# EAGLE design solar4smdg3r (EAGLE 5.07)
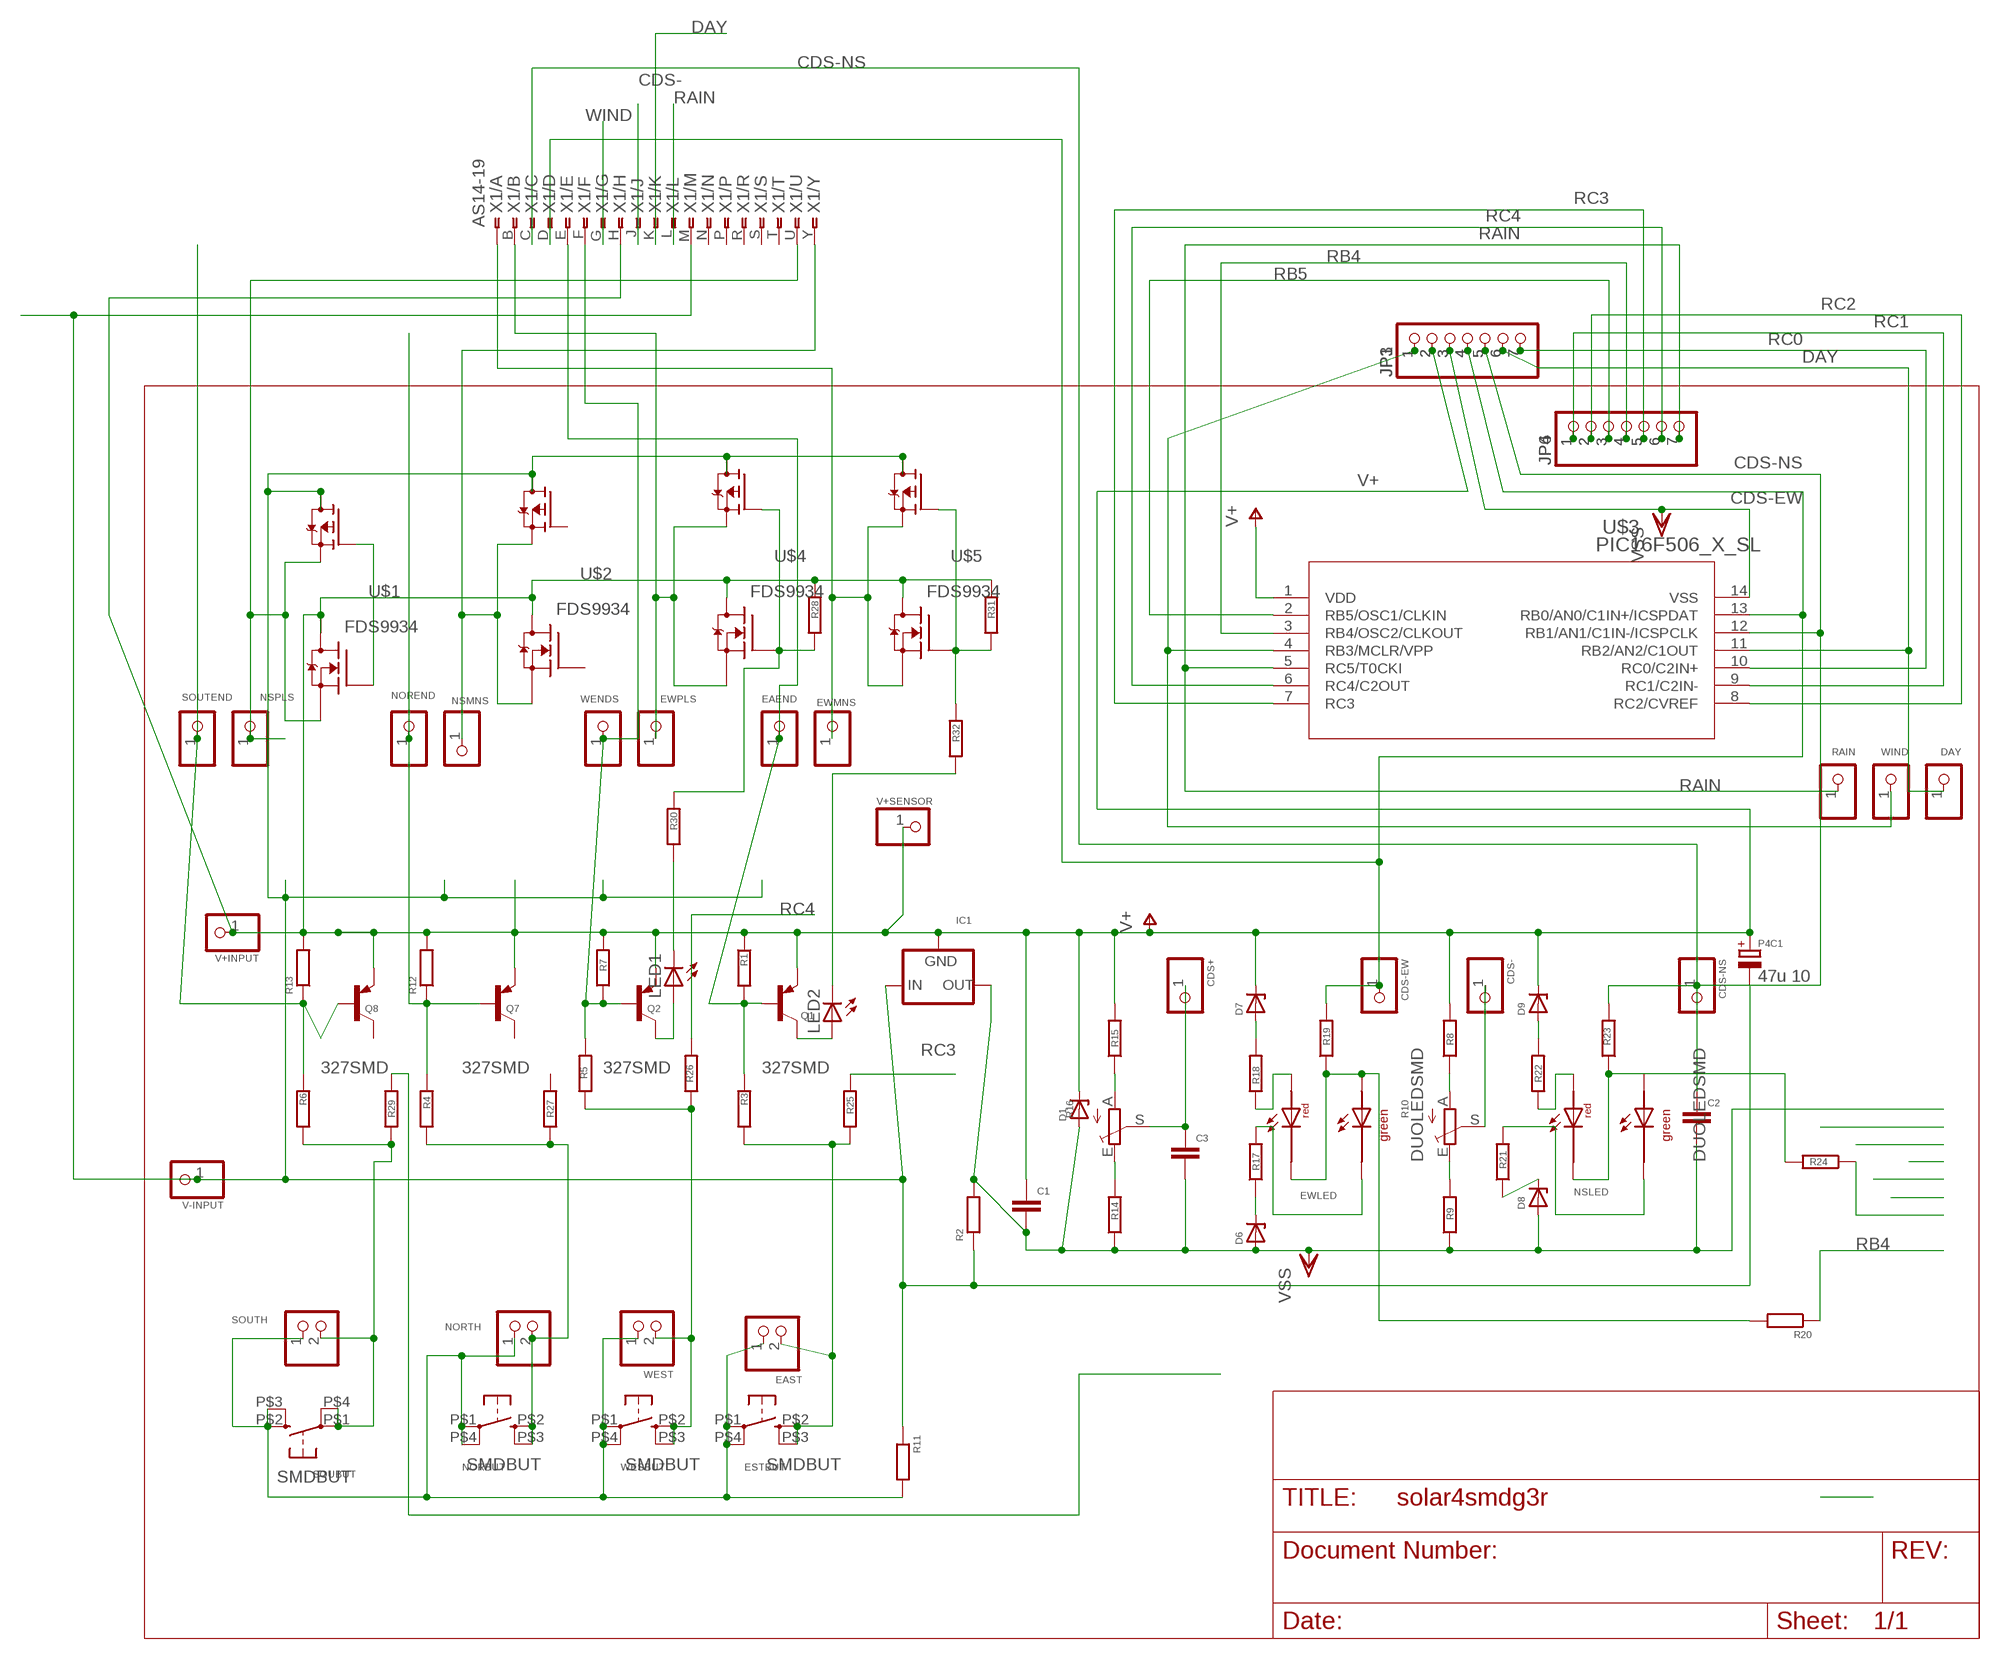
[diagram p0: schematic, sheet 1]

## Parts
C1  C-EUC1206  [C1206]
C2  C-EUC1206  [C1206]
C3  C-EUC1206  [C1206]
CDS+  PINHD-1X1INCH  [1X01]
CDS-  PINHD-1X1INCH  [1X01]
CDS-EW  PINHD-1X1INCH  [1X01]
CDS-NS  PINHD-1X1INCH  [1X01]
D1  ZENER-DIODESOD80C  [SOD80C]
D6  ZENER-DIODESOD80C  [SOD80C]
D7  ZENER-DIODESOD80C  [SOD80C]
D8  ZENER-DIODESOD80C  [SOD80C]
D9  ZENER-DIODESOD80C  [SOD80C]
DAY  PINHD-1X1INCH  [1X01]
EAEND  PINHD-1X1INCH  [1X01]
EAST  PINHD-1X2STR  [1X02]
ESTBUT  SMDBUT  [SMD10/5]
EWLED  DUOLEDSMD  [DUOLEDSMD]
EWMNS  PINHD-1X10MM6  [1X01M]
EWPLS  PINHD-1X10MM6  [1X01M]
IC1  79LXX  [79LXX]
JP1  PINHD-1X7  [1X07]
JP3  PINHD-1X7  [1X07]
JP4  PINHD-1X7  [1X07]
JP6  PINHD-1X7  [1X07]
LED1  LEDCHIPLED_1206  [CHIPLED_1206]
LED2  LEDCHIPLED_1206  [CHIPLED_1206]
NORBUT  SMDBUT  [SMD10/5]
NOREND  PINHD-1X1INCH  [1X01]
NORTH  PINHD-1X2STR  [1X02]
NSLED  DUOLEDSMD  [DUOLEDSMD]
NSMNS  PINHD-1X1INCH  [1X01]
NSPLS  PINHD-1X10MM6  [1X01M]
P4C1  47u 10  CPOL-EUE5-8.5  [E5-8,5]
Q1  327SMD  BC327SMD  [SOT23-BEC]
Q2  327SMD  BC327SMD  [SOT23-BEC]
Q7  327SMD  BC327SMD  [SOT23-BEC]
Q8  327SMD  BC327SMD  [SOT23-BEC]
R1  R-EU_R0805  [R0805]
R2  R-EU_R0805  [R0805]
R3  R-EU_R0805  [R0805]
R4  R-EU_R1206  [R1206]
R5  R-EU_R0805  [R0805]
R6  R-EU_R1206  [R1206]
R7  R-EU_R0805  [R0805]
R8  R-EU_R1206  [R1206]
R9  R-EU_R0805  [R0805]
R10  TRIM_EU-CA6V  [CA6V]
R11  R-EU_R0805  [R0805]
R12  R-EU_R1206  [R1206]
R13  R-EU_R0805  [R0805]
R14  R-EU_R1206  [R1206]
R15  R-EU_R1206  [R1206]
R16  TRIM_EU-CA6V  [CA6V]
R17  R-EU_R1206  [R1206]
R18  R-EU_R1206  [R1206]
R19  R-EU_R0805  [R0805]
R20  R-EU_R0805  [R0805]
R21  R-EU_R1206  [R1206]
R22  R-EU_R1206  [R1206]
R23  R-EU_R0805  [R0805]
R24  R-EU_R0805  [R0805]
R25  R-EU_R0805  [R0805]
R26  R-EU_R0805  [R0805]
R27  R-EU_R0805  [R0805]
R28  R-EU_R0805  [R0805]
R29  R-EU_R0805  [R0805]
R30  R-EU_R0805  [R0805]
R31  R-EU_R0805  [R0805]
R32  R-EU_R0805  [R0805]
RAIN  PINHD-1X1INCH  [1X01]
SOUBUT  SMDBUT  [SMD10/5]
SOUTEND  PINHD-1X1INCH  [1X01]
SOUTH  PINHD-1X2STR  [1X02]
U$1  FDS9934  [SO-8]
U$2  FDS9934  [SO-8]
U$3  PIC16F506_X_SL  [SOIC14_N_MC]
U$4  FDS9934  [SO-8]
U$5  FDS9934  [SO-8]
V+INPUT  PINHD-1X1INCH  [1X01]
V+SENSOR  PINHD-1X10MM6  [1X01M]
V-INPUT  PINHD-1X10MM6  [1X01M]
WENDS  PINHD-1X1INCH  [1X01]
WESBUT  SMDBUT  [SMD10/5]
WEST  PINHD-1X2STR  [1X02]
WIND  PINHD-1X1INCH  [1X01]
X1  AS14-19  AS14-19OLIVE  [Y28M-19TK]

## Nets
CDS-: CDS-.1 R10.S X1.J
CDS-EW: CDS-EW.1 JP1.4 JP3.4 R19.2 U$3.13(RB0/AN0/C1IN+/ICSPDAT) X1.D
CDS-NS: C2.1 CDS-NS.1 JP1.5 JP3.5 R23.2 U$3.12(RB1/AN1/C1IN-/ICSPCLK) X1.C
DAY: DAY.1 JP1.6 JP3.6 U$3.11(RB2/AN2/C1OUT) X1.K
MOTO1: EWPLS.1 U$4.1(Q1S) U$4.3(Q2S) X1.B
MOTOR1: NSPLS.1 U$1.1(Q1S) U$1.3(Q2S) X1.U
MOTOR2: NSMNS.1 U$2.1(Q1S) U$2.3(Q2S) X1.Y
MOTOR3: EWMNS.1 U$5.1(Q1S) U$5.3(Q2S) X1.A
N$1: R9.2 R10.E
N$6: EWLED.AGRN EWLED.CRED R19.1 R20.2
N$9: R6.1 R29.1 SOUBUT.P$1(P) SOUBUT.P$4(P1) SOUTH.2
N$10: LED1.A Q2.C
N$11: EAST.2 ESTBUT.P$2(S) ESTBUT.P$3(S1) R3.1 R25.1
N$13: R24.1
N$14: D7.A R18.2
N$17: NORBUT.P$2(S) NORBUT.P$3(S1) NORTH.2 R4.1 R27.1
N$18: R8.1 R10.A
N$19: Q8.B R6.2 R13.1 SOUTEND.1
N$20: NOREND.1 Q7.B R4.2 R12.1
N$21: R14.2 R16.E
N$22: R15.1 R16.A
N$23: C3.1 CDS+.1 R16.S
N$25: EWLED.ARED R18.1
N$27: D6.C R17.1
N$28: EWLED.CGRN R17.2
N$29: EAST.1 ESTBUT.P$1(P) ESTBUT.P$4(P1) NORBUT.P$1(P) NORBUT.P$4(P1) NORTH.1 R11.2 SOUBUT.P$2(S) SOUBUT.P$3(S1) SOUTH.1 WESBUT.P$1(P) WESBUT.P$4(P1) WEST.1
N$30: NSLED.AGRN NSLED.CRED R23.1 R24.2
N$32: Q2.B R5.2 R7.1 WENDS.1 X1.F
N$33: EAEND.1 Q1.B R1.2 R3.2 X1.E
N$35: R29.2
N$37: LED2.A Q1.C
N$39: R5.1 R26.1 WESBUT.P$2(S) WESBUT.P$3(S1) WEST.2
N$41: D9.A R22.2
N$42: NSLED.ARED R22.1
N$43: D8.C R21.1
N$44: NSLED.CGRN R21.2
N$50: U$1.2(Q1G) U$1.4(Q2G)
N$51: LED1.C R30.1
N$54: R28.1 R30.2 U$4.2(Q1G) U$4.4(Q2G)
N$55: R31.1 R32.2 U$5.2(Q1G) U$5.4(Q2G)
N$56: LED2.C R32.1
RAIN: JP4.7 JP6.7 RAIN.1 U$3.5(RC5/T0CKI) X1.L
RB4: JP4.4 JP6.4 R20.1 U$3.3(RB4/OSC2/CLKOUT)
RB5: JP4.3 JP6.3 U$3.2(RB5/OSC1/CLKIN)
RC0: JP1.7 JP3.7 U$3.10(RC0/C2IN+)
RC1: JP4.1 JP6.1 U$3.9(RC1/C2IN-)
RC2: JP4.2 JP6.2 U$3.8(RC2/CVREF)
RC3: JP4.5 JP6.5 R25.2 U$3.7(RC3)
RC4: JP4.6 JP6.6 R26.2 U$3.6(RC4/C2OUT)
V+: C1.1 D1.C D7.C D9.C IC1.GND JP1.2 JP3.2 P4C1.+ Q1.E Q2.E Q7.E Q8.E R1.1 R7.2 R8.2 R12.2 R13.2 R15.2 R28.2 R31.2 U$1.7(Q1D2) U$1.8(Q1D1) U$2.7(Q1D2) U$2.8(Q1D1) U$3.1(VDD) U$4.7(Q1D2) U$4.8(Q1D1) U$5.7(Q1D2) U$5.8(Q1D1) V+INPUT.1 V+SENSOR.1 X1.H
V-: IC1.IN P4C1.- R2.1 R11.1 U$1.5(Q2D2) U$1.6(Q2D) U$2.5(Q2D2) U$2.6(Q2D) U$4.5(Q2D2) U$4.6(Q2D) U$5.5(Q2D2) U$5.6(Q2D) V-INPUT.1 X1.M
VSS: C1.2 C2.2 C3.2 D1.A D6.A D8.A IC1.OUT JP1.3 JP3.3 R2.2 R9.1 R14.1 U$3.14(VSS)
WIND: JP1.1 JP3.1 U$3.4(RB3/MCLR/VPP) WIND.1 X1.G
Unconnected: Q7.C Q8.C R27.2 U$2.2(Q1G) U$2.4(Q2G) X1.N X1.P X1.R X1.S X1.T

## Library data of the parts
C1-C3 = rcl-2:C-EU: CAPACITOR, European symbol
CDS+ CDS- CDS-EW CDS-NS DAY EAEND EWMNS EWPLS NOREND NSMNS NSPLS RAIN SOUTEND V+INPUT V+SENSOR V-INPUT WENDS WIND = pinhead(2):PINHD-1X1: PIN HEADER
D1 D6-D9 = diode-1:ZENER-DIODE: Z-Diode
EAST NORTH SOUTH WEST = pinhead:PINHD-1X2: PIN HEADER
ESTBUT NORBUT SOUBUT WESBUT = switch-omron:SMDBUT
EWLED NSLED = led:DUOLEDSMD
IC1 = v-reg:79LXX: VOLTAGE REGULATOR
JP1 JP3 JP4 JP6 = pinhead:PINHD-1X7: PIN HEADER
LED1 LED2 = led:LED: LED
P4C1 = rcl:CPOL-EU: POLARIZED CAPACITOR, European symbol
Q1 Q2 Q7 Q8 = transistor-pnp:BC327*: PNP Transistror
R1-R9 R11-R15 R17-R32 = rcl-2:R-EU_: RESISTOR, European symbol
R10 R16 = pot:TRIM_EU-: POTENTIOMETER
U$1 U$2 U$4 U$5 = transistor-fet:FDS9934
U$3 = pic16f506mc:PIC16F506_X_SL
X1 = con-deutsch:AS14-19: DEUTSCH Connector

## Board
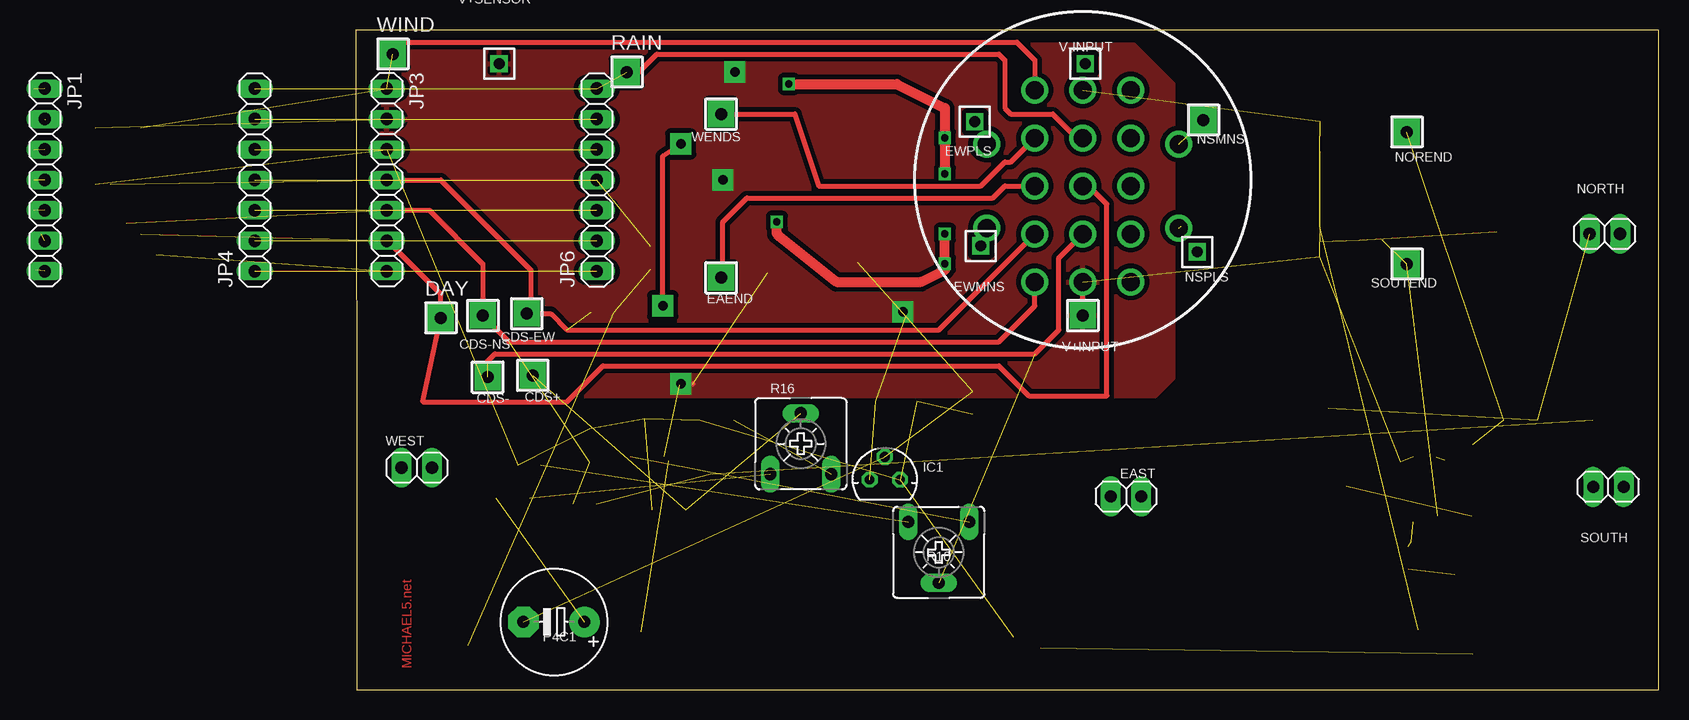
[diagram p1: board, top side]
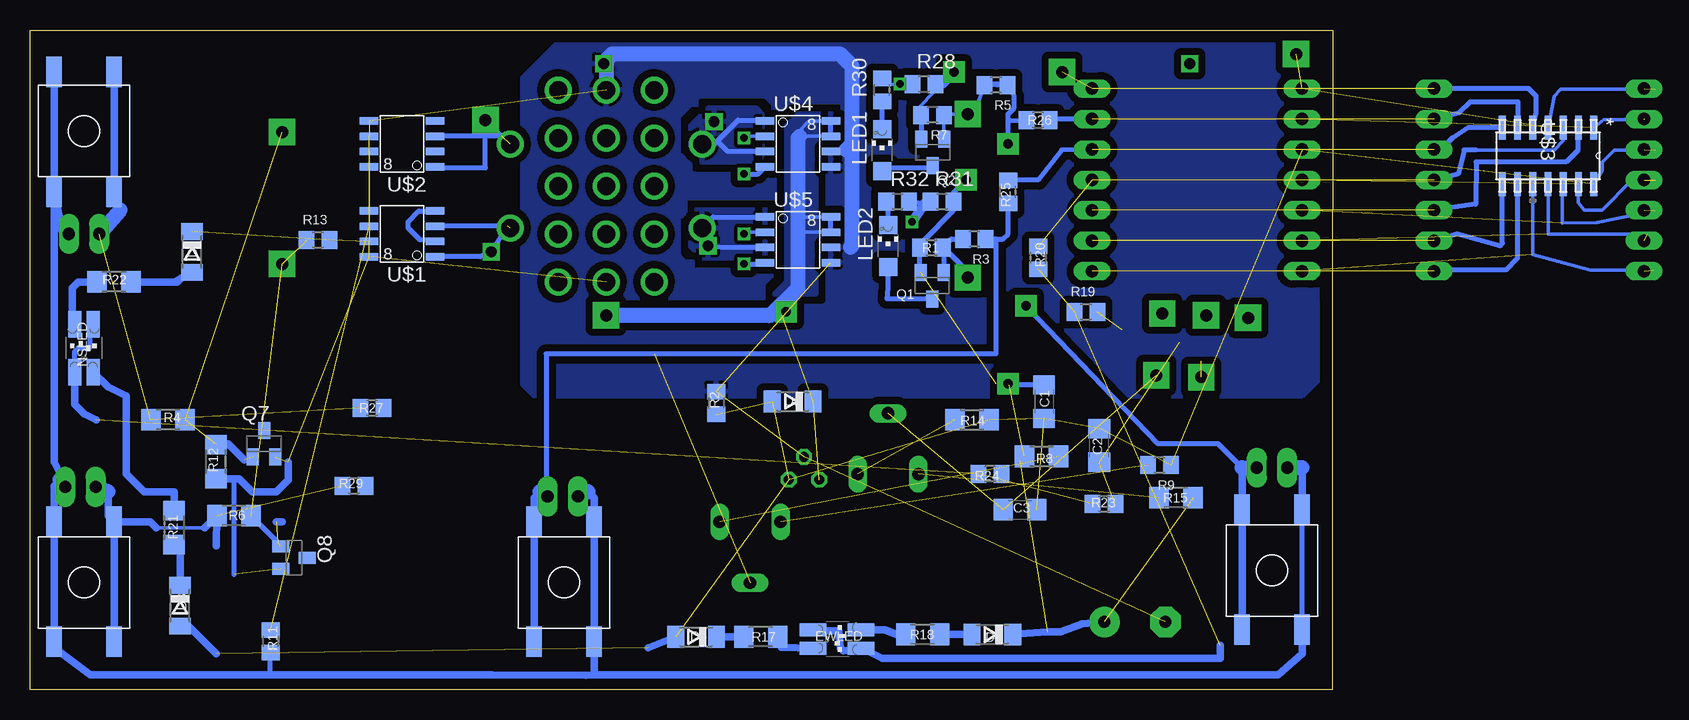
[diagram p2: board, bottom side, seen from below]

Size 108.57 x 55 mm. Coordinates in mm from the lower left corner, seen from the top.
Outline: 0.07,0 108.57,0 108.57,55 0,55 0.07,25 0.07,0
Copper layers (1*16): Top 0.035mm / dielectric 1.5mm / Bottom 0.035mm
Design rules "default *": minimum track width 40mil, minimum drill 30mil, track to track 8mil, track to pad 8mil, pad to pad 8mil, via to via 8mil, smd to smd 8mil, copper to edge 40mil, drill to drill 8mil, minimum pad ring 10mil, minimum via ring 8mil, stop-mask expansion 4mil, vias tented up to drill 0mil, thermal gap 10mil

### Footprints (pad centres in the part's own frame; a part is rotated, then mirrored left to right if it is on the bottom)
C1206 = smd 1.6 x 1.8: 1 -1.4,0; 2 1.4,0
1X01 = drill 1 pad 2.184 square: 1 0,0
SOD80C = smd 1.4 x 1.8: A 1.7,0; C -1.7,0
1X02 = drill 1.016 pad 1.676 long: 1 -1.27,0; 2 1.27,0
SMD10/5 = smd 1.27 x 2.54: P$1 -2.5,0; P$2 2.5,0; P$3 2.5,10; P$4 -2.5,10
DUOLEDSMD = smd 1.067 x 2.184: AGRN 0.77,1.95; ARED -0.77,1.95; CGRN 0.77,-2.05; CRED -0.77,-2.05
1X01M = drill 0.914 square: 1 0,0
79LXX = drill 0.813 octagon: GND -1.27,0; IN 0,1.905; OUT 1.27,0
1X07 = drill 1.016 long: 1 -7.62,0; 2 -5.08,0; 3 -2.54,0; 4 0,0; 5 2.54,0; 6 5.08,0; 7 7.62,0
CHIPLED_1206 = smd 1.5 x 1.5: A 0,-1.75; C 0,1.75
E5-8,5 = drill 1 pad 2.54 round: + -2.54,0 | drill 1 pad 2.54 octagon: - 2.54,0
SOT23-BEC = smd 1 x 1.4: B -0.95,-1.1; C 0,1.1; E 0.95,-1.1
R0805 = smd 1.3 x 1.5: 1 -0.95,0; 2 0.95,0
R1206 = smd 1.6 x 1.803: 1 -1.422,0; 2 1.422,0
CA6V = drill 1.016 long: A -2.54,-2.54; E 2.54,-2.54; S 0,2.54
SO-8 = smd 1.524 x 0.61: 1 -2.743,1.905; 2 -2.743,0.635; 3 -2.743,-0.635; 4 -2.743,-1.905; 5 2.743,-1.905; 6 2.743,-0.635; 7 2.743,0.635; 8 2.743,1.905
SOIC14_N_MC = smd 1.981 x 0.559: 1 -2.362,3.81; 2 -2.362,2.54; 3 -2.362,1.27; 4 -2.362,0; 5 -2.362,-1.27; 6 -2.362,-2.54; 7 -2.362,-3.81; 8 2.362,-3.81; 9 2.362,-2.54; 10 2.362,-1.27; 11 2.362,0; 12 2.362,1.27; 13 2.362,2.54; 14 2.362,3.81
Y28M-19TK = drill 1.5 pad 2.184 round: A -8,-3.5; B -8,3.5; C -4,-8; D -4,-4; E -4,0; F -4,4; G -4,8; H 0,-8; J 0,-4; K 0,0; L 0,4; M 0,8; N 4,-8; P 4,-4; R 4,0; S 4,4; T 4,8; U 8,-3.5; Y 8,3.5

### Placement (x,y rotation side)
C1  24.07,24 270 bottom
C2  19.46,20.35 90 bottom
C3  26.07,15 0 bottom
CDS+  14.72,26.2 0 top
CDS-  10.97,26.05 90 top
CDS-EW  14.22,31.35 0 top
CDS-NS  10.57,31.2 90 top
D1  45.02,24.02 180 bottom
D6  53.07,4.4 180 bottom
D7  28.37,4.6 180 bottom
D8  96.07,7 270 bottom
D9  95.07,36.5 270 bottom
DAY  7.07,31 0 top
EAEND  30.42,34.35 90 top
EAST  64.17,16.1 0 top
ESTBUT  64.07,14 180 bottom
EWLED  41.27,4.2 270 bottom
EWMNS  52.07,37 90 top
EWPLS  51.57,47.35 90 top
IC1  44.07,17.5 0 top
JP1  not placed on the board
JP3  2.57,42.5 270 top
JP4  -8.43,42.5 90 top  (outside the outline)
JP6  20.07,42.5 90 top
LED1  37.57,45 0 bottom
LED2  37.07,37 0 bottom
NORBUT  104.07,41.5 0 bottom
NOREND  87.57,46.5 0 top
NORTH  104.07,38 180 top
NSLED  104.07,28.5 0 bottom
NSMNS  70.62,47.5 0 top
NSPLS  70.12,36.5 0 top
P4C1  16.49,5.64 180 top
Q1  33.38,33.67 180 bottom
Q2  33.34,44.79 180 bottom
Q7  89.07,20.5 0 bottom
Q8  86.57,11 270 bottom
R1  33.46,36.85 0 bottom
R2  51.39,23.89 270 bottom
R3  29.88,37.56 180 bottom
R4  97.07,22.5 0 bottom
R5  28.07,50.4 180 bottom
R6  91.57,14.5 0 bottom
R7  33.36,47.91 180 bottom
R8  24.28,19.44 180 bottom
R9  14.44,18.71 180 bottom
R10  48.56,11.44 180 top
R11  88.52,4.02 270 bottom
R12  93.07,19 270 bottom
R13  84.57,37.5 0 bottom
R14  30.07,22.5 180 bottom
R15  13.07,16 0 bottom
R16  37.07,20.5 0 top
R17  47.67,4.4 0 bottom
R18  34.17,4.6 0 bottom
R19  20.57,31.5 0 bottom
R20  24.57,36 270 bottom
R21  96.57,13.5 90 bottom
R22  101.57,34 0 bottom
R23  19.07,15.5 0 bottom
R24  28.57,18 180 bottom
R25  27.07,41.5 90 bottom
R26  24.57,47.5 0 bottom
R27  80.07,23.5 0 bottom
R28  34.07,50.5 0 bottom
R29  81.57,17 0 bottom
R30  37.57,50 90 bottom
R31  32.57,40.7 0 bottom
R32  36.27,40.7 0 bottom
RAIN  22.57,51.5 0 top
SOUBUT  104.07,14 180 bottom
SOUTEND  87.57,35.5 0 top
SOUTH  104.37,16.9 180 top
U$1  77.57,38 180 bottom
U$2  77.57,45.5 180 bottom
U$3  -17.93,44.5 270 bottom  (outside the outline)
U$4  44.57,45.5 0 bottom
U$5  44.57,37.5 0 bottom
V+INPUT  60.57,31.2 90 top
V+SENSOR  11.92,52.2 90 top
V-INPUT  60.77,52.2 90 top
WENDS  30.42,48 90 top
WESBUT  5.07,15 180 bottom
WEST  5.07,18.5 0 top
WIND  3.07,53 0 top
X1  60.57,42 0 top

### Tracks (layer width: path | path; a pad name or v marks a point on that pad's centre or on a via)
CDS-  (2 unrouted)
  Top 0.406: X1.J 58.57,36 58.57,30 56.57,28 11.57,28 10.97,27.4
CDS-EW  (3 unrouted)
  Top 0.406: JP3.4 7.07,42.5 14.57,35 14.57,31.7 CDS-EW.1 16.22,31.35 17.57,30 48.57,30 X1.D
  Bottom 0.305: U$3.13 -20.43,40.6 -20.93,40 -22.43,40 -24.89,42.46 -26.86,42.46
CDS-NS  (4 unrouted)
  Top 0.406: X1.C 56.57,32 53.57,29 12.77,29 CDS-NS.1 10.57,35.5 6.11,39.96 JP3.5
  Bottom 0.305: U$3.12 -19.13,41.31 -19.13,38.9 -22.01,38.92 -26.86,39.92
DAY  (2 unrouted)
  Top 0.406: JP3.6 2.99,37 3.07,37 7.07,33 DAY.1 5.57,24 17.57,24 20.57,27 53.57,27 56.07,24.5 62.57,24.5 62.57,40.5 61.07,42 X1.K
  Bottom 0.305: U$3.11 -17.93,38 -26.24,38
MOTO1
  Bottom 0.406: X1.B 51.57,45.5 51.32,45.75 | 51.32,45.75 49.57,47.5 47.41,47.5 U$4.1 | U$4.3 50.44,44.87 51.32,45.75
  pour Bottom (isolate 0.305): 47.57,47.5 47.57,48 48.07,48.5 52.07,48.5 53.57,47 53.57,45 52.57,44 48.07,44 47.57,44.5
MOTOR1  (1 unrouted)
  Bottom 0.406: U$1.3 68.75,38.63 NSPLS.1 71.02,36.09 U$1.1
MOTOR2  (1 unrouted)
  Bottom 0.406: U$2.1 74.97,43.59 75.07,43.5 70.62,43.5 NSMNS.1 69.25,46.13 U$2.3
MOTOR3
  Bottom 0.406: U$5.3 50.94,36.87 EWMNS.1 51.66,39.41 U$5.1
  pour Bottom (isolate 0.305): 47.07,40 53.07,40 53.57,39.5 53.57,37 52.57,36 47.57,36 47.07,36.5
N$1  (1 unrouted)
N$6  (2 unrouted)
  Bottom 0.61: EWLED.CRED 42.95,4.9 41.17,4.9 41.07,3.5 40.8,3.23 EWLED.AGRN 38.8,3.23 37.57,2.6 9.37,2.6 9.37,3.7
N$9  (1 unrouted)
  Bottom 0.305: 98.07,13.5 93.99,13.5
  Bottom 0.61: SOUBUT.P$1 98.57,14 98.07,13.5 | 93.99,13.5 R6.1 93.07,12 | SOUBUT.P$4 SOUBUT.P$1 | SOUBUT.P$1 102.07,14.5 102.07,16.5
  Bottom 1.27: 102.07,16.5 SOUTH.2
N$10
  Bottom 0.406: Q2.C 33.54,43.5 37.07,43.5 LED1.A
N$11
  Bottom 0.406: R25.1 27.07,38 27.51,37.56 28.07,37.56 | 28.07,37.56 R3.1 | EAST.2 65.57,16.23 65.57,28 28.07,28 28.07,37.56
  Bottom 0.61: ESTBUT.P$3 ESTBUT.P$2 66.57,16 66.07,16.5
  Bottom 1.27: EAST.2 66.07,16.5
N$14
  Bottom 0.61: D7.A R18.2
N$17  (2 unrouted)
  Bottom 0.61: NORBUT.P$2 NORBUT.P$3 | NORBUT.P$2 101.57,41 | 101.07,40 NORBUT.P$2
  Bottom 1.27: NORTH.2 101.07,40
N$18  (1 unrouted)
N$19  (4 unrouted)
  Bottom 0.406: 87.92,12.27 R6.2
  Bottom 0.61: 87.57,14 88.07,14
N$20  (3 unrouted)
  Bottom 0.61: 90.72,19.15 92.07,20.5 92.99,20.5 R12.1
N$21  (1 unrouted)
N$22  (1 unrouted)
N$23  (2 unrouted)
N$25
  Bottom 0.61: R18.1 35.49,4.42 36.07,4.5 37.35,5 EWLED.ARED
N$27
  Bottom 0.61: R17.1 D6.C
N$28
  Bottom 0.61: EWLED.CGRN 45.98,3.53 R17.2
N$29
  Bottom 0.406: WESBUT.P$4 WESBUT.P$1 | R11.2 88.57,2.6 88.57,1.25
  Bottom 0.61: WESBUT.P$1 2.57,18.5 | 61.57,1.25 ESTBUT.P$4 ESTBUT.P$1 61.57,16 62.07,16.5 | 61.57,1.25 4.57,1.25 2.57,3 WESBUT.P$4 | 61.57,1.25 62.27,1.2 70.07,1.23 73.57,1.25 88.57,1.25 103.57,1.25 106.57,3.5 SOUBUT.P$3 SOUBUT.P$2 106.57,17 106.07,17.5 | SOUTH.1 106.07,18 106.57,19 NORBUT.P$1 | NORBUT.P$1 106.07,39 | NORBUT.P$1 NORBUT.P$4
  Bottom 1.27: 2.57,18.5 WEST.1 | 62.07,16.5 EAST.1 | 106.07,17.5 SOUTH.1 | 106.07,39 NORTH.1
N$30  (2 unrouted)
  Bottom 0.406: NSLED.CRED 104.84,28.23 104.57,28.5 103.57,28.5 103.57,30.18 NSLED.AGRN
  Bottom 0.61: NSLED.CRED 104.84,23.77 104.07,23 103.07,22.5
N$32
  Top 0.406: X1.F 54.57,44 54.07,44 52.07,42 38.57,42 36.57,48 WENDS.1
  Bottom 0.305: Q2.B 32.41,45.91 R7.1 32.33,48 WENDS.1 30.42,48.35 29.57,49 29.07,50.35 R5.2
N$33
  Top 0.406: X1.E 54.07,42 53.07,41 32.57,41 30.57,39 30.57,34.5 EAEND.1
  Bottom 0.406: 32.43,36.86 Q1.B | 32.43,36.86 32.43,37.27 R1.2 31.8,37.56 R3.2 | 32.43,36.86 30.57,35 30.57,34.5 EAEND.1
N$37
  Bottom 0.406: Q1.C 37.14,32.57 37.07,33.5 LED2.A
N$39  (via drill 0.8 pad 1.78)
  Top 0.406: v27.07,45.5 25.57,44.5 v25.57,32
  Bottom 0.406: R5.1 29.02,50.5 27.07,50.5 26.57,49.5 26.57,48.5 27.07,48 27.07,47.45 | 27.07,47.45 R26.1 | v27.07,45.5 27.07,47.45 | v25.57,32 14.57,20.5 9.57,20.5 7.57,18.5
  Bottom 0.61: WESBUT.P$3 WESBUT.P$2 7.57,18.5
  Bottom 1.27: 7.57,18.5 WEST.2
N$41
  Bottom 0.61: D9.A 95.97,34.32 | 95.97,34.32 96.57,34 | R22.2 96.29,34 95.97,34.32
N$42
  Bottom 0.61: R22.1 104.57,34 105.07,33.5 105.07,30.68 NSLED.ARED
N$43
  Bottom 0.61: D8.C 96.07,11.58 R21.1
N$44
  Bottom 0.61: R21.2 96.57,16.5 99.07,16.5 100.57,18 100.57,24.5 102.07,25.22 NSLED.CGRN
N$50
  Bottom 0.406: U$1.4 76.16,39.91 77.07,39 77.07,38.5 76.07,37.5 74.96,37.5 U$1.2
N$51
  Bottom 0.406: LED1.C R30.1
N$54  (via drill 0.6)
  Top 0.813: v36.07,50.5 45.07,50.5 49.07,48.5 v49.07,46 v49.07,43
  Bottom 0.305: U$4.2 48.94,46.13 v49.07,46 | R30.2 37.12,50.5 v36.07,50.5 R28.1
  Bottom 0.406: U$4.4 47.91,43 v49.07,43
N$55  (via drill 0.6)
  Top 0.406: 49.07,35 v49.07,35.5
  Top 0.813: 49.07,35 47.07,34 40.07,34 35.07,38 v35.07,39 | v49.07,35.5 v49.07,38
  Bottom 0.305: U$5.2 48.94,38.13 v49.07,38
  Bottom 0.406: R32.2 34.07,40.5 R31.1 | U$5.4 47.41,35.5 v49.07,35.5
  Bottom 0.813: v35.07,39 34.07,40.5
N$56
  Bottom 0.406: LED2.C 37.07,40 R32.1
RAIN  (2 unrouted)
  Top 0.406: RAIN.1 23.57,51.5 25.07,53 53.57,53 54.07,52.5 54.07,48.5 54.57,48 58.07,48 60.07,46 X1.L
  Bottom 0.406: JP4.7 -16.31,50.12 -16.93,49.5 -16.93,48.09 U$3.5
RB4  (2 unrouted)
  Bottom 0.305: U$3.3 -19.2,45.77 -18.43,45 -11.93,45
  Bottom 0.406: -11.93,45 -10.93,45 -10.43,43 JP4.4
RB5  (1 unrouted)
  Bottom 0.406: JP4.3 -11.89,40.46 -11.93,44 -19.43,44 -20.43,45 -20.43,46.82 U$3.2
RC0  (2 unrouted)
  Bottom 0.305: U$3.10 -16.66,36.27 -21.43,35 -26.7,35
RC1  (1 unrouted)
  Bottom 0.406: U$3.9 -15.39,35.96 -14.43,35 -8.55,35 JP4.1 | JP6.1 20.9,34.88
RC2  (1 unrouted)
  Bottom 0.406: U$3.8 -14.12,37.19 -13.93,37 -10.35,38 JP4.2
RC3  (1 unrouted)
  Bottom 0.406: U$3.7 -11.29,46.86 -9.93,46 -9.47,45.5 JP4.5 | JP6.5 22.61,45 24.57,42.5 27.07,42.5 R25.2
RC4  (1 unrouted)
  Bottom 0.406: JP4.6 -10.51,48.08 -11.43,49 -15.43,49 -15.43,46.9 U$3.6 | R26.2 23.54,47.58 JP6.6
V+  (via drill 0.8 pad 1.78)  (17 unrouted)
  Top 0.406: V+INPUT.1 X1.H | v27.07,25.5 28.07,25.5
  Bottom 0.305: 44.44,46.13 U$4.7 | U$4.8 43.66,47.41 44.57,46.5 44.57,46 | U$5.8 44.48,39.41 44.57,39.5 | U$5.7 44.44,38.13 44.57,38 | R28.2 33.12,49.95 34.57,48.5 34.57,48.17 R7.2 | U$3.1 -22.56,47.54 -25.89,47.54 -26.43,47 -26.46,47
  Bottom 0.406: R8.2 26.07,19.07 | 91.57,9.6 91.57,17.58 | Q2.E 34.31,46.41 R7.2 | U$5.7 U$5.8 | U$4.7 U$4.8 | v45.57,31.5 45.87,31.2 47.07,31.2 | v30.57,42.5 31.62,41.45 R31.2 31.62,39.95 34.07,37.5 34.07,37.19 R1.1 34.41,34.85 Q1.E | C1.1 26.97,25.4 v27.07,25.5
  Bottom 0.61: D7.C 23.77,4.8 22.67,4.8 20.89,5.5 P4C1.+ | R12.2 91.57,17.58 91.15,17.58 90.07,16.5 88.07,16.5 87.07,17.5 87.07,19
  Bottom 0.813: R28.2 32.57,50.5 v31.57,51.5
  Bottom 1.27: V+INPUT.1 47.07,31.2 46.87,31.2 44.57,33.5 44.57,38 44.57,39.5 44.57,46 44.44,46.13
  pour Bottom (isolate 0.61): 41.57,48 44.57,48 45.57,47 45.57,34 46.57,33 43.07,33 43.07,46 41.57,47.5
  pour Top (isolate 0.406): 2.57,54 64.57,54 68.07,50.5 68.07,26 66.57,24.5 1.07,24.5
V-  (8 unrouted)
  Bottom 1.27: X1.M 60.57,52.5 60.07,53 41.07,53 40.07,52 40.07,45.5 | 40.07,45.5 40.57,45 | 40.2,36.87 40.07,37 40.07,45.5
  pour Bottom (isolate 0.61, rank 4): 2.07,54 64.57,54 67.57,51 67.57,25.5 66.57,24.5 2.57,24.5 1.07,26
VSS  (12 unrouted)
  Bottom 0.305: U$3.14 -22.43,43.33 -22.43,44 -23.43,45 -26.86,45
  Bottom 0.61: D8.A 95.37,5.3 93.07,3 | D6.A 57.07,3.5
WIND  (3 unrouted)
  Top 0.406: WIND.1 4.07,54 55.07,54 56.57,52.5 X1.G
  Bottom 0.305: U$3.4 -18.43,49.5 -19.01,50.08 -26.86,50.08

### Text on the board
Top: MICHAEL5.net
